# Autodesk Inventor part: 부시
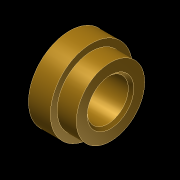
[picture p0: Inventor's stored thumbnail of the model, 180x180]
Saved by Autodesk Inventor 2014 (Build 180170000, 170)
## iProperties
Company: 한국ATC센터
Created: 2014-08
Part Number: 부시
Document SubType Name: Modeling
Designer: KYOUNG IL JANG
Density: 7.86 g/cm^3
Checked By: KYOUNG IL JANG
Material: 강철, 연강
Appearance: 황동 - 새틴
Mass: 50.2336 g
Surface Area: 30.183 cm^2
Volume: 6.39105 cm^3
Author: KYOUNG IL JANG
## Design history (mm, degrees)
sketch "스케치1"
  geometry: L1 (0, 0)-(15, 0); L2 (0, 7.5)-(15, 7.5); L3 (15, 7.5)-(15, 12.5); L4 (15, 12.5)-(8, 12.5); L5 (8, 12.5)-(8, 15); L6 (8, 15)-(0, 15); L7 (0, 15)-(0, 7.5)
  constraints: 14 end point, 4 parallel, 2 vertical alignment, 1 horizontal, 1 perpendicular, 1 vertical
  dimensions: "d0" = 15 distance of L1.start L1.end; "d1" = 15 diameter of L2 L1; "d2" = 25 diameter of L4 L1; "d3" = 8 distance of L5.end L6.end; "d4" = 30 diameter of L6 L1
revolve "회전1" sketch "스케치1" stored, may be unused: angle "d5" = 90 deg
chamfer "모따기1" distance "d6" = 1; stored, may be unused: second distance "d7" = 2, angle "d8" = 45 deg
node "솔리드1"
